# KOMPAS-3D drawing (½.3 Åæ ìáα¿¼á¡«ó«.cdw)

Views: Вид 1
Referenced files in C:\Program Files\ASCON\KOMPAS-3D V10\Sys\: SPDS.lcs, Graphic.lcs
Referenced files in \\F-server\проектирование\Проекты\РЗА и ПА Тюменские РС\4. Проект\ЭП\Туринская\Рабочая документация\: план располодения оборудования на ПС.cdw
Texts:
  Текст на чертеже
  Размерные надписи
  Шероховатость
  Линия-выноска #1
  Линия-выноска #2
  Линия-выноска #3
  Отклонения формы и база
  Заголовок таблицы
  Ячейка таблицы
  Стрелка вида
  Обозначение изменения
  Фигурная скобка
  Номер узла
  Марка координационной оси
  VRCB
  Выносная надпись
  Обозначение узла
  Марка/позиционное обозначение с линией-выноской
  Марка/позиционное обозначение на линии
  Марка/позиционное обозначение без линии-выноски
  Лит-Масса-Масштаб
  Материал-Предприятие
  Title Specification
  Body Specification ( left align )
  Body Specificaton ( centered )
  Без имени
  Normal
  heading 1
  Знак Знак Знак Знак Знак Знак
  Verdana
  Body Text
  MS Sans Serif
  Txt
  Simplex
  TXT
  Обычный
  Термин
  Список определений
  Адрес
  Цитаты
  Форматированный
  Courier New
  Z-конец формы
  Z-начало формы
  Additional DXF text style 0
  Абзац Знак
  Body Text 3
  Title
  ТекстШаг1
  Шрифт 2.5
  Заголовки
  txt
  heading 2
  AGOpus
  footer
  Денис
  RUSTXT
  Обычный (веб)
  ООббыыччнныыйй
  Definition Term
  Definition List
  Address
  Blockquote
  Preformatted
  z-Bottom of Form
  z-Top of Form
  header
  NormalParagraphStyle
  ссылки
  Подпись в квадратике
  табл
  цепи
  Маркировка
  клеммы, контакты
  тексты табл
  Тексты. 3,2
  ЗОНА_привяз
  текст переноса
  ТТееррммиинн
  ССппииссоокк ооппррееддееллеенниийй
  ААддрреесс
  ЦЦииттааттыы
  ФФооррммааттиирроовваанннныыйй
  Z-ккооннеецц ффооррммыы
  Z-ннааччааллоо ффооррммыы
  GOST 2.304 type A
  rustxt
  heading 8
  heading 3
  heading 6
  heading 7
  russ
  heading 4
  heading 5
  heading 9
  HeliosLight
  Pa3
  Pa1
  Три с половиной
  style2
  Table Contents
  Table Heading
  ГОСТ_МНЕ
  ESK - Обозначение
  маркировка
  ISOCP
  ROMANS
  SIMPLEX
  Текст 3,5
  Tahoma
  текст табл
  Пояснения 2
  romans
  gif
  ISOCPEUR
  CM12
  Клеммник текст
  Пояснения
  Ссылки
  подписи
  Аппараты
  ячейка табл.
  Состав чартежа
  CM16+18
  FR5
  Subtitle
  CNBNDG+TimesNewRoman
  Courier New Cyr
  Normal (Web)
  romanc
  eskd1
  Pa15
  Pa18
  CC С?т?и?л?ь? П?о? ц?е?н?т?р?у?
  ошиновка
  лотки
  Топосъемка
  Примечания:
  1. Для нужд строительства (размещение задействованного в строительстве персонала, обеспечение
  электроэнергией) использовать временные мобильные инвентарные здания;
  2. При выполнении всех строительно-монтажных работ на площадке необходимо руководствоваться
  требованиями СНиП 12-03-2001 "Безопасность труда в строительстве. Общие требования",
  СНиП 12-04-2002 "Безопасность труда в строительстве. Строительное производство", а также
  ПОТ-РМ-016-2001/РД 153-34.0-03.150-00 "Межотраслевые правила по охране труда (правила
  безопасности) при эксплуатации электроустановок";
  3. Наружное освещение строительной площадки осуществляется за счет существующего освещения;
  4. Под временные сооружения (поз. II, III и IV) устраивается площадка из дорожных плит ПД 60-20 на
  щебеночном основании толщиной 15см;
  5. На период строительства для электроснабжения временных зданий и сооружений использовать ди-
  зельную электростанцию. Прокладку  кабеля от дизельной электростанции до вагончиков выполнить
  в воздушном исполнении в гофрированной трубе диаметром 30 мм, на вагончиках кабель закрепить
  скобами. Щиток временного электроснабжения навесить на стенку вагона-дома для отдыха рабочих;
  6. При выполнении монтажных работ использовать инвентарные лестницы и леса;
  7. Тонкой линией изображено существующее оборудование, замена которого проектом не предусматри-
  вается, утолщенной - вновь устанавливаемое оборудование.
  8. На паспорте-стенде строительного объекта  должен быть план пожарной защиты с нанесенными
  строящимися и вспомогательными зданиями и сооружениями, въездами, подъездами, местонахождениями
  водоисточников, средств пожаротушения и связи (согласно ППБ-01-03 п.575);
  9. Условные обозначения см. 16/01-ПОС,л.1.
  10. Грузовысотные характеристики КМУ ИНМАН ИМ-150 см. 16/01-ПОС,л.7.
  Экспликация зданий и сооружений
  Номер
  на плане
  Постоянные здания и сооружения
  КРУН 10 кВ
  Трансформатор 1Т, маслоприемник
  Существующее
  Существующий
  Временные здания и сооружения
  III
  Вагон-дом для кратковременного отдых рабочих
  Уборная
  Дизельная электростанция
  Контейнеры для ТБО (0,75м 3 ) и жидких хоз.-быт.стоков(1м 3 )
  «Екатерина» 9,0х3,0
  Туалетная кабина "Люкс"
  ОАО ПКТИпромстрой
  h.забора 62.44
  h.забора 62.66
  кр.61.26
  н.пр.68.50
  h.забора 62.58
  н.пр.74.66
  н.пр.67.77
  н.пр.67.53
  h.забора 62.74
  н.пр.68.02
  н.пр.68.07
  скв.№4
  каб.лоток
  тр-р
  зру
  гр.
  КМУ ИНМАН ИМ-150
  K5LT_BASIC_RGB_0_0_255_THICK_0.6
  K5LT_BASIC_RGB_0_0_255_THICK_0.2
  K5LT_AXLED_RGB_255_128_0_SC_1_THICK_0.09
  POLYLINE_STYLE_0.18_RGB_168_80_0
  CONTI_RGB_0_0_0_THICK_0.18
  CONTI_RGB_51_51_51_THICK_0.18
  CONTI_RGB_51_51_51_THICK_0.4
  CONTI_RGB_0_0_0_THICK_0.4
  Стили документа
  Бортовой автомобиль КамАЗ 43114-027-02
  АТ ППР#010#0104
  ГИП
  Н.контр.
  Гл.спец.
  Провер.
  Разраб.
  Перезавод ВЛ на ПС Тюмень. Реконструкция устройств
  РЗ и ПА на обратных концах отходящих ВЛ,
  ВОЛС Тюменского ТПО
  ПС 110/10 кВ Нариманово
  Матвеев
  Ромин
  Шашерин
  Королева
  Строительный генеральный план
  Общие технические условия на средний ремонт
Dimensions and other numbers on the sheet: 16/01-ПОС; 7; 2,5; 1,8; 2.5; 3,2_; 3.5; 3,2; 2,5 (контакты, клеммы); 3,2 (надписи); 3,2 (Зоны); 5; 2,5_01; 2,5_3; 3,5_01; 3,5_tabl; 5_заголовок; 2,3_; 3,2_зона не привяз; 3,5; 3.2 маркировка; 3,2 элементы; 3,2 линия; 3,2 таблица; 2,5 грязносинь; 2.5 курсив; 2.5_Э5_надписи; 2.5_Э5_ссылки; 2.5_кабель; 3.2; 2.5 надписи; 3 и 5; 5,0_белый_подчёркнутый; 3.2 фиол; 3.2 (текст); 1; 2; 10,6; 61.11; 60.94; 61.04; 60.85; 60.98; 60.79; 62.72; 63.28; 62.34; 61.74; 63.33; 63.98; 62.37; 63.23; 62.32; 62.08; 63.24; 63.25; 63.86; 60.82; 62.36; 62.98; 62.46; 62.86; 61.98; 62.90; 61.40; 61.46; 62.87; 61.78; 61.90; 61.19; 62.04; 62.52; 62.85; 63.10; 63.11; 61.55; 61.06; 60.88; 61.64; 62.99; 60.80; 62.25; 61.03; 61.49; 61.16; 60.99; 61.02; 61.05; 61.08; 60.96; 61.20; 626250; 1каб.10кВ; 60.56; 4; 05.13; 3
